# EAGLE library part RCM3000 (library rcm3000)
RCM3000 Rabbit 3000 PCB footprint with Symbol. Created by Matty Cunningham 18 June 2003 manxmat@manx.net
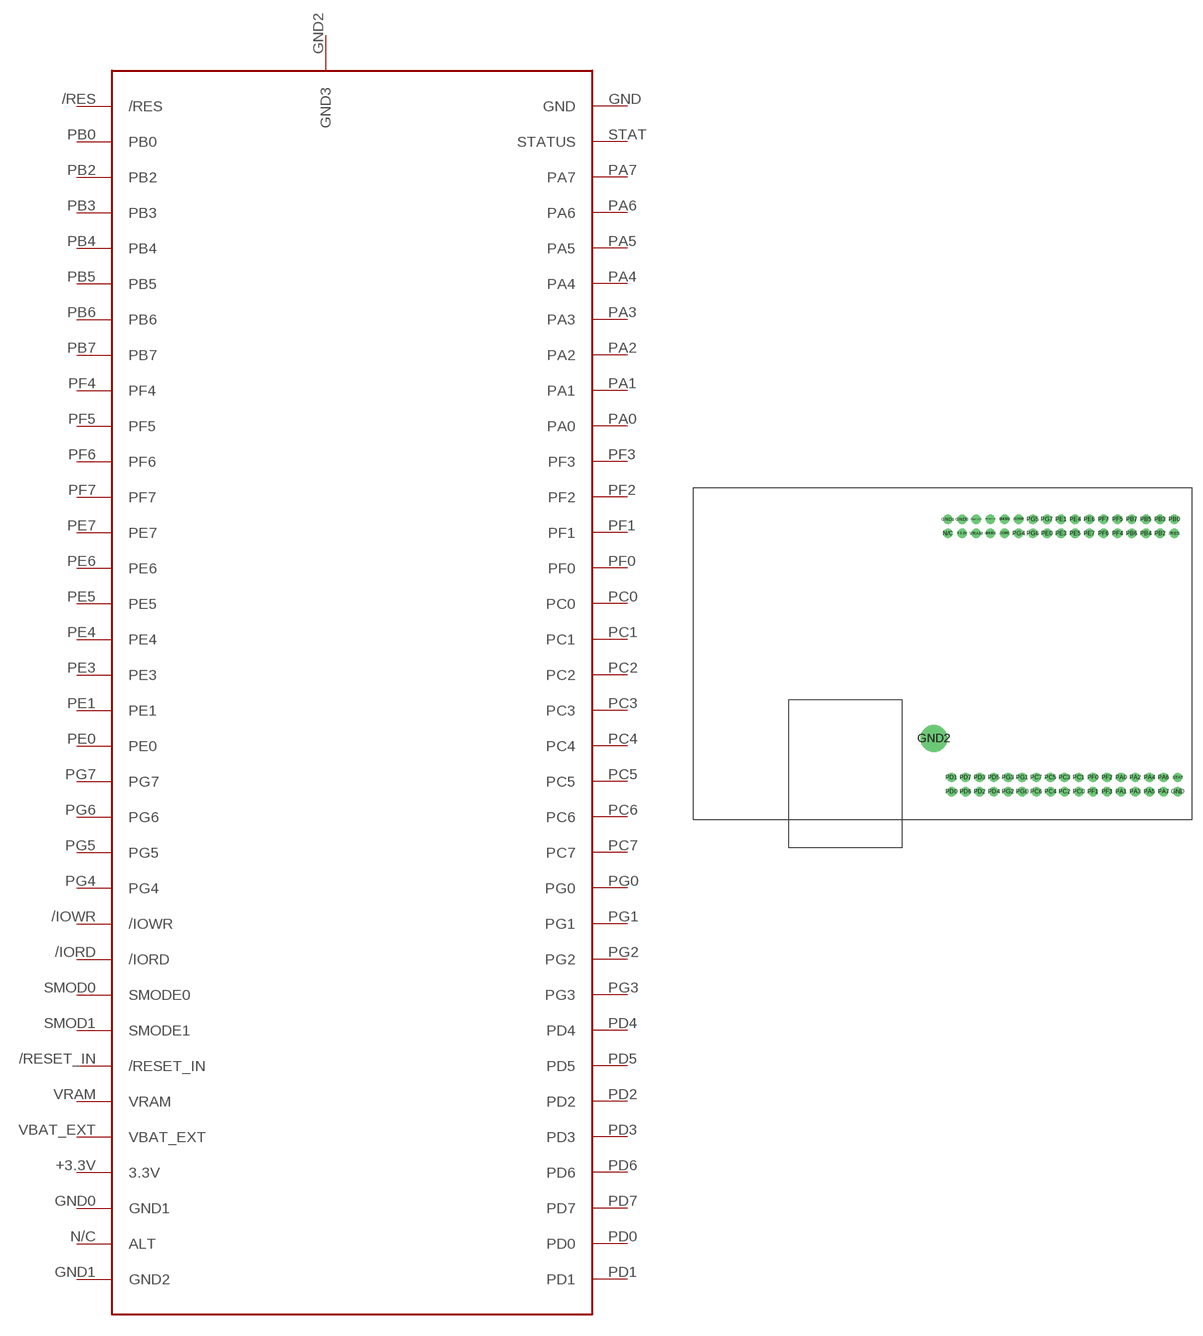
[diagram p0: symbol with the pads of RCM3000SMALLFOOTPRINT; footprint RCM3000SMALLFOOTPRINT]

Designator prefix -

## RCM3000  [RCM3000SMALLFOOTPRINT]
+3.3V  3.3V
/IORD  /IORD
/IOWR  /IOWR
/RES  /RES
/RESET_IN  /RESET_IN
GND  GND
GND0  GND1
GND1  GND2
GND2  GND3
N/C  ALT
PA0  PA0
PA1  PA1
PA2  PA2
PA3  PA3
PA4  PA4
PA5  PA5
PA6  PA6
PA7  PA7
PB0  PB0
PB2  PB2
PB3  PB3
PB4  PB4
PB5  PB5
PB6  PB6
PB7  PB7
PC0  PC0
PC1  PC1
PC2  PC2
PC3  PC3
PC4  PC4
PC5  PC5
PC6  PC6
PC7  PC7
PD0  PD0
PD1  PD1
PD2  PD2
PD3  PD3
PD4  PD4
PD5  PD5
PD6  PD6
PD7  PD7
PE0  PE0
PE1  PE1
PE3  PE3
PE4  PE4
PE5  PE5
PE6  PE6
PE7  PE7
PF0  PF0
PF1  PF1
PF2  PF2
PF3  PF3
PF4  PF4
PF5  PF5
PF6  PF6
PF7  PF7
PG0  PG0
PG1  PG1
PG2  PG2
PG3  PG3
PG4  PG4
PG5  PG5
PG6  PG6
PG7  PG7
SMOD0  SMODE0
SMOD1  SMODE1
STAT  STATUS
VBAT_EXT  VBAT_EXT
VRAM  VRAM

## Footprint RCM3000SMALLFOOTPRINT (pad centres in mm)
RCM3000 Rabbit 3000 Core module footprint
drill 0.813 pad 1.27 round: +3.3V -9,4.5; /IORD -3,4.5; /IOWR -1,6.5; /RES 21,4.5; /RESET_IN -5,6.5; GND 21.5,-32; GND0 -9,6.5; GND1 -11,6.5; N/C -11,4.5; PA0 13.5,-30; PA1 13.5,-32; PA2 15.5,-30; PA3 15.5,-32; PA4 17.5,-30; PA5 17.5,-32; PA6 19.5,-30; PA7 19.5,-32; PB0 21,6.5; PB2 19,4.5; PB3 19,6.5; PB4 17,4.5; PB5 17,6.5; PB6 15,4.5; PB7 15,6.5; PC0 7.5,-32; PC1 7.5,-30; PC2 5.5,-32; PC3 5.5,-30; PC4 3.5,-32; PC5 3.5,-30; PC6 1.5,-32; PC7 1.5,-30; PD0 -10.5,-32; PD1 -10.5,-30; PD2 -6.5,-32; PD3 -6.5,-30; PD4 -4.5,-32; PD5 -4.5,-30; PD6 -8.5,-32; PD7 -8.5,-30; PE0 3,4.5; PE1 5,6.5; PE3 5,4.5; PE4 7,6.5; PE5 7,4.5; PE6 9,6.5; PE7 9,4.5; PF0 9.5,-30; PF1 9.5,-32; PF2 11.5,-30; PF3 11.5,-32; PF4 13,4.5; PF5 13,6.5; PF6 11,4.5; PF7 11,6.5; PG0 -0.5,-32; PG1 -0.5,-30; PG2 -2.5,-32; PG3 -2.5,-30; PG4 -1,4.5; PG5 1,6.5; PG6 1,4.5; PG7 3,6.5; SMOD0 -3,6.5; SMOD1 -5,4.5; STAT 21.5,-30; VBAT_EXT -7,6.5; VRAM -7,4.5
drill 2.54 pad 3.81 round: GND2 -13,-24.5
